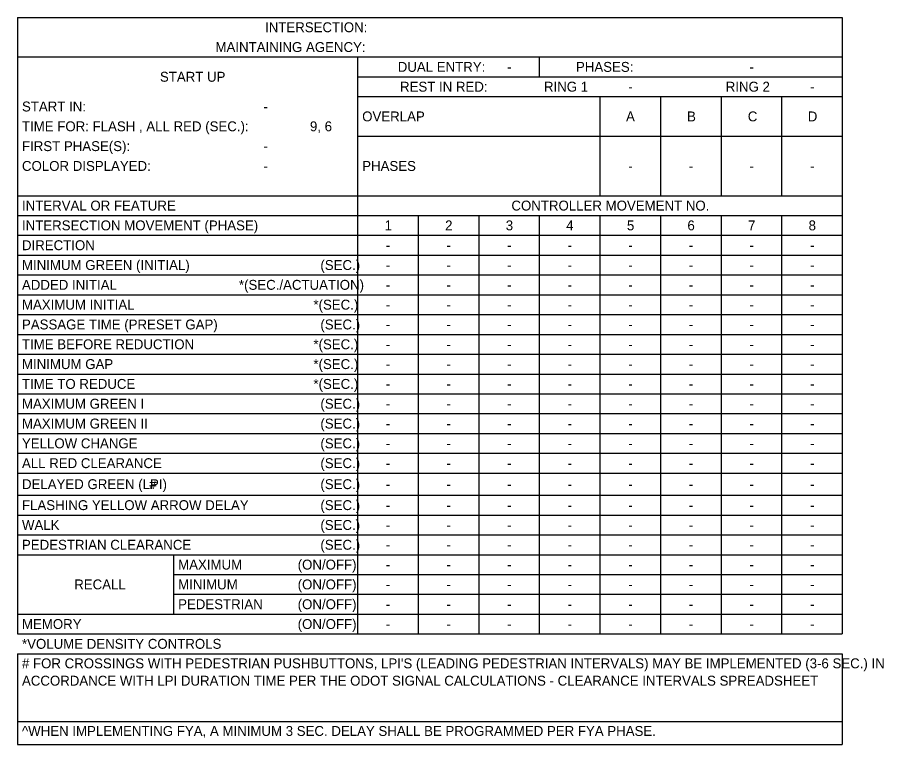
# Model space of a CAD drawing. Extents: x -513 to 1005, y -278 to 699.
# Drawn here: x 230.5 to 475.5, y -278.3 to -72.7 of the extents above; entities that cross this region are included whole.
import ezdxf

# ---------------------------------------------------------------- set-up
doc = ezdxf.new("R2010")
doc.units = 0
doc.layers.add('SG_P_Poles', color=7, linetype='Continuous')

msp = doc.modelspace()

# ---------------------------------------------------------------- linework, layer by layer
at = {"layer": 'SG_P_Poles'}
for p, q in [((230.52, -72.74), (463.74, -72.74)), ((230.52, -72.74), (230.52, -247)), ((463.74, -72.74), (463.74, -247)), ((230.52, -83.94), (463.74, -83.94)), ((326.7, -83.94), (326.7, -247)), ((378.09, -83.94), (378.09, -89.54)), ((326.7, -89.54), (463.74, -89.54)), ((326.7, -95.14), (463.74, -95.14)), ((395.22, -95.14), (395.22, -123.14)), ((412.35, -95.14), (412.35, -123.14)), ((429.48, -95.14), (429.48, -123.14)), ((446.61, -95.14), (446.61, -123.14)), ((326.7, -106.34), (463.74, -106.34)), ((230.52, -123.14), (463.74, -123.14)), ((230.52, -128.74), (463.74, -128.74)), ((343.83, -128.74), (343.83, -247)), ((360.96, -128.74), (360.96, -247)), ((378.09, -128.74), (378.09, -247)), ((395.22, -128.74), (395.22, -247)), ((412.35, -128.74), (412.35, -247)), ((429.48, -128.74), (429.48, -247)), ((446.61, -128.74), (446.61, -247)), ((230.52, -134.34), (463.74, -134.34)), ((230.52, -139.94), (463.74, -139.94)), ((230.52, -145.54), (463.74, -145.54)), ((230.52, -151.14), (463.74, -151.14)), ((230.52, -156.74), (463.74, -156.74)), ((230.52, -162.34), (463.74, -162.34)), ((230.52, -167.94), (463.74, -167.94)), ((230.52, -173.54), (463.74, -173.54)), ((230.52, -179.14), (463.74, -179.14)), ((230.52, -184.74), (463.74, -184.74)), ((230.52, -190.34), (463.74, -190.34)), ((230.52, -195.94), (463.74, -195.94)), ((230.52, -201.54), (463.74, -201.54)), ((230.52, -207.8), (463.74, -207.8)), ((230.52, -213.4), (463.74, -213.4)), ((230.52, -219), (463.74, -219)), ((230.52, -224.6), (463.74, -224.6)), ((274.66, -224.6), (274.66, -241.4)), ((274.66, -230.2), (463.74, -230.2)), ((274.66, -235.8), (463.74, -235.8)), ((230.52, -241.4), (463.74, -241.4)), ((230.52, -247), (463.74, -247)), ((230.52, -252.6), (463.74, -252.6)), ((230.52, -252.6), (230.52, -278.29)), ((463.74, -252.6), (463.74, -278.29)), ((230.52, -271.7), (463.74, -271.7)), ((230.52, -278.29), (463.74, -278.29))]:
    msp.add_line(p, q, dxfattribs=at)

# ---------------------------------------------------------------- texts
for s, p in [('INTERSECTION:', (300.56, -76.94)), ('MAINTAINING AGENCY:', (286.54, -82.54)), ('DUAL ENTRY:', (338.07, -88.14)), ('PHASES:', (388.46, -88.14)), ('START UP', (270.84, -90.94)), ('-', (368.98, -88.14)), ('-', (437.5, -88.14)), ('REST IN RED:', (338.71, -93.74)), ('RING 1', (379.41, -93.74)), ('-', (403.24, -93.74)), ('RING 2', (430.8, -93.74)), ('-', (454.63, -93.74)), ('START IN:', (231.83, -99.34)), ('-', (300.13, -99.34)), ('OVERLAP', (328.02, -102.14)), ('A', (402.61, -102.14)), ('B', (419.87, -102.14)), ('C', (437.04, -102.14)), ('D', (454, -102.14)), ('TIME FOR: FLASH , ALL RED (SEC.):', (231.83, -104.94)), ('9, 6', (313.25, -104.94)), ('FIRST PHASE(S):', (231.83, -110.54)), ('-', (300.13, -110.54)), ('COLOR DISPLAYED:', (231.83, -116.14)), ('-', (300.13, -116.14)), ('PHASES', (328.02, -116.14)), ('-', (403.24, -116.14)), ('-', (420.37, -116.14)), ('-', (437.5, -116.14)), ('-', (454.63, -116.14)), ('INTERVAL OR FEATURE', (231.83, -127.34)), ('CONTROLLER MOVEMENT NO.', (370.21, -127.34)), ('INTERSECTION MOVEMENT (PHASE)', (231.83, -132.94)), ('1', (334.35, -132.94)), ('2', (351.47, -132.94)), ('3', (368.61, -132.94)), ('4', (385.69, -132.94)), ('5', (402.87, -132.94)), ('6', (419.97, -132.94)), ('7', (437.12, -132.94)), ('8', (454.23, -132.94)), ('DIRECTION', (231.83, -138.54)), ('-', (334.72, -138.54)), ('-', (351.85, -138.54)), ('-', (368.98, -138.54)), ('-', (386.11, -138.54)), ('-', (403.24, -138.54)), ('-', (420.37, -138.54)), ('-', (437.5, -138.54)), ('-', (454.63, -138.54)), ('MINIMUM GREEN (INITIAL)', (231.83, -144.14)), ('(SEC.)', (316.2, -144.14)), ('-', (334.72, -144.14)), ('-', (351.85, -144.14)), ('-', (368.98, -144.14)), ('-', (386.11, -144.14)), ('-', (403.24, -144.14)), ('-', (420.37, -144.14)), ('-', (437.5, -144.14)), ('-', (454.63, -144.14)), ('ADDED INITIAL', (231.83, -149.74)), ('*(SEC./ACTUATION)', (293.17, -149.74)), ('-', (334.72, -149.74)), ('-', (351.85, -149.74)), ('-', (368.98, -149.74)), ('-', (386.11, -149.74)), ('-', (403.24, -149.74)), ('-', (420.37, -149.74)), ('-', (437.5, -149.74)), ('-', (454.63, -149.74)), ('MAXIMUM INITIAL', (231.83, -155.34)), ('*(SEC.)', (314.23, -155.34)), ('-', (334.72, -155.34)), ('-', (351.85, -155.34)), ('-', (368.98, -155.34)), ('-', (386.11, -155.34)), ('-', (403.24, -155.34)), ('-', (420.37, -155.34)), ('-', (437.5, -155.34)), ('-', (454.63, -155.34)), ('PASSAGE TIME (PRESET GAP)', (231.83, -160.94)), ('(SEC.)', (316.2, -160.94)), ('-', (334.72, -160.94)), ('-', (351.85, -160.94)), ('-', (368.98, -160.94)), ('-', (386.11, -160.94)), ('-', (403.24, -160.94)), ('-', (420.37, -160.94)), ('-', (437.5, -160.94)), ('-', (454.63, -160.94)), ('TIME BEFORE REDUCTION', (231.83, -166.54)), ('*(SEC.)', (314.23, -166.54)), ('-', (334.72, -166.54)), ('-', (351.85, -166.54)), ('-', (368.98, -166.54)), ('-', (386.11, -166.54)), ('-', (403.24, -166.54)), ('-', (420.37, -166.54)), ('-', (437.5, -166.54)), ('-', (454.63, -166.54)), ('MINIMUM GAP', (231.83, -172.14)), ('*(SEC.)', (314.23, -172.14)), ('-', (334.72, -172.14)), ('-', (351.85, -172.14)), ('-', (368.98, -172.14)), ('-', (386.11, -172.14)), ('-', (403.24, -172.14)), ('-', (420.37, -172.14)), ('-', (437.5, -172.14)), ('-', (454.63, -172.14)), ('TIME TO REDUCE', (231.83, -177.74)), ('*(SEC.)', (314.23, -177.74)), ('-', (334.72, -177.74)), ('-', (351.85, -177.74)), ('-', (368.98, -177.74)), ('-', (386.11, -177.74)), ('-', (403.24, -177.74)), ('-', (420.37, -177.74)), ('-', (437.5, -177.74)), ('-', (454.63, -177.74)), ('MAXIMUM GREEN I', (231.83, -183.34)), ('(SEC.)', (316.2, -183.34)), ('-', (334.72, -183.34)), ('-', (351.85, -183.34)), ('-', (368.98, -183.34)), ('-', (386.11, -183.34)), ('-', (403.24, -183.34)), ('-', (420.37, -183.34)), ('-', (437.5, -183.34)), ('-', (454.63, -183.34)), ('MAXIMUM GREEN II', (231.83, -188.94)), ('(SEC.)', (316.2, -188.94)), ('-', (334.72, -188.94)), ('-', (351.85, -188.94)), ('-', (368.98, -188.94)), ('-', (386.11, -188.94)), ('-', (403.24, -188.94)), ('-', (420.37, -188.94)), ('-', (437.5, -188.94)), ('-', (454.63, -188.94)), ('YELLOW CHANGE', (231.83, -194.54)), ('(SEC.)', (316.2, -194.54)), ('-', (334.72, -194.54)), ('-', (351.85, -194.54)), ('-', (368.98, -194.54)), ('-', (386.11, -194.54)), ('-', (403.24, -194.54)), ('-', (420.37, -194.54)), ('-', (437.5, -194.54)), ('-', (454.63, -194.54)), ('ALL RED CLEARANCE', (231.83, -200.14)), ('(SEC.)', (316.2, -200.14)), ('-', (334.72, -200.14)), ('-', (351.85, -200.14)), ('-', (368.98, -200.14)), ('-', (386.11, -200.14)), ('-', (403.24, -200.14)), ('-', (420.37, -200.14)), ('-', (437.5, -200.14)), ('-', (454.63, -200.14)), ('DELAYED GREEN (LPI) ', (231.83, -206.07)), ('#', (267.81, -206.07)), ('(SEC.)', (316.2, -206.07)), ('-', (334.72, -206.07)), ('-', (351.85, -206.07)), ('-', (368.98, -206.07)), ('-', (386.11, -206.07)), ('-', (403.24, -206.07)), ('-', (420.37, -206.07)), ('-', (437.5, -206.07)), ('-', (454.63, -206.07)), ('FLASHING YELLOW ARROW DELAY', (231.83, -212)), ('(SEC.)', (316.2, -212)), ('-', (334.72, -212)), ('-', (351.85, -212)), ('-', (368.98, -212)), ('-', (386.11, -212)), ('-', (403.24, -212)), ('-', (420.37, -212)), ('-', (437.5, -212)), ('-', (454.63, -212)), ('WALK', (231.83, -217.6)), ('(SEC.)', (316.2, -217.6)), ('-', (334.72, -217.6)), ('-', (351.85, -217.6)), ('-', (368.98, -217.6)), ('-', (386.11, -217.6)), ('-', (403.24, -217.6)), ('-', (420.37, -217.6)), ('-', (437.5, -217.6)), ('-', (454.63, -217.6)), ('PEDESTRIAN CLEARANCE', (231.83, -223.2)), ('(SEC.)', (316.2, -223.2)), ('-', (334.72, -223.2)), ('-', (351.85, -223.2)), ('-', (368.98, -223.2)), ('-', (386.11, -223.2)), ('-', (403.24, -223.2)), ('-', (420.37, -223.2)), ('-', (437.5, -223.2)), ('-', (454.63, -223.2)), ('MAXIMUM', (275.98, -228.8)), ('(ON/OFF)', (309.78, -228.8)), ('-', (334.72, -228.8)), ('-', (351.85, -228.8)), ('-', (368.98, -228.8)), ('-', (386.11, -228.8)), ('-', (403.24, -228.8)), ('-', (420.37, -228.8)), ('-', (437.5, -228.8)), ('-', (454.63, -228.8)), ('RECALL', (246.61, -234.4)), ('MINIMUM', (275.98, -234.4)), ('(ON/OFF)', (309.78, -234.4)), ('-', (334.72, -234.4)), ('-', (351.85, -234.4)), ('-', (368.98, -234.4)), ('-', (386.11, -234.4)), ('-', (403.24, -234.4)), ('-', (420.37, -234.4)), ('-', (437.5, -234.4)), ('-', (454.63, -234.4)), ('PEDESTRIAN', (275.98, -240)), ('(ON/OFF)', (309.78, -240)), ('-', (334.72, -240)), ('-', (351.85, -240)), ('-', (368.98, -240)), ('-', (386.11, -240)), ('-', (403.24, -240)), ('-', (420.37, -240)), ('-', (437.5, -240)), ('-', (454.63, -240)), ('MEMORY', (231.83, -245.6)), ('(ON/OFF)', (309.78, -245.6)), ('-', (334.72, -245.6)), ('-', (351.85, -245.6)), ('-', (368.98, -245.6)), ('-', (386.11, -245.6)), ('-', (403.24, -245.6)), ('-', (420.37, -245.6)), ('-', (437.5, -245.6)), ('-', (454.63, -245.6)), ('*VOLUME DENSITY CONTROLS', (231.83, -251.2)), ("# FOR CROSSINGS WITH PEDESTRIAN PUSHBUTTONS, LPI'S (LEADING PEDESTRIAN INTERVALS) MAY BE IMPLEMENTED (3-6 SEC.) IN ", (231.83, -256.71)), ('ACCORDANCE WITH LPI DURATION TIME PER THE ODOT SIGNAL CALCULATIONS - CLEARANCE INTERVALS SPREADSHEET', (231.83, -261.61)), ('^ WHEN IMPLEMENTING FYA, A MINIMUM 3 SEC. DELAY SHALL BE PROGRAMMED PER FYA PHASE.', (231.83, -275.82))]:
    msp.add_text(s, height=2.8, dxfattribs=at).set_placement(p)

doc.saveas('drawing.dxf')
